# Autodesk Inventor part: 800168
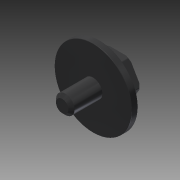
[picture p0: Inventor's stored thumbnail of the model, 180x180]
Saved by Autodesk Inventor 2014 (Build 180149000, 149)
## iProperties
Created: 2007-10
Part Number: 800168
Document SubType Name: Modeling
Designer: AL
Density: 8.08 g/cm^3
Mass: 16.5411 g
Surface Area: 16.0193 cm^2
Volume: 2.04717 cm^3
Material: Stainless Steel
Description: SCREW
Appearance: Rubber - Black - Version 1.1
Component Category: Fasteners
Author: AL
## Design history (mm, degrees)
sketch "Sketch1"
  geometry: L1 (0, -13.662)-(0, 11.973) reference; L2 (-11.878, 0)-(16.593, 0) reference; L3 (0, 7)-(5.25, 7); L4 (5.25, 7)-(5.25, 2); L5 (5.25, 2)-(12.375, 2); L6 (12.5, 1.875)-(12.5, 0.125); L7 (12.375, 0)-(3, 0); L8 (3, 0)-(3, -9); L9 (3, -9)-(2, -10); L10 (2, -10)-(0, -10); A1 r 0.125 centre (12.375, 1.875) between (12.5, 1.875) and (12.375, 2); A2 r 0.125 centre (12.375, 0.125) between (12.375, 0) and (12.5, 0.125); 3 further points
  constraints: 16 end point, 6 point on line, 5 parallel, 4 point on circle, 4 tangent, 2 centre point, 2 perpendicular, 1 collinear, 1 equal radius
  dimensions: "d0" = 1 horizontal distance of L8.end L9.end; "d1" = 1 horizontal distance of L8.end L9.end; "d2" = 6 diameter of L8 L1; "d3" = 25 diameter of L6 L1; "d4" = 10.5 diameter of L4 L1; "d5" = 2 distance between parallel lines of L5 L7; "d7" = 10 distance between parallel lines of L10 L7; "d10" = 5 distance between parallel lines of L5 L3; "d12" = 0.125 radius of A1
revolve "Revolution1" sketch "Sketch1" stored, may be unused: angle "d11" = 90 deg
workplane "Work Plane1"
sketch "Sketch2"
  geometry: L1 (10.874, 0)-(-10.569, 0) reference; L2 (0, -9.1)-(0, 9.1) reference; L3 (-3.753, -6.5)-(-7.506, 0); L4 (-7.506, 0)-(-3.753, 6.5); L5 (-3.753, 6.5)-(3.753, 6.5); L6 (3.753, 6.5)-(7.506, 0); L7 (7.506, 0)-(3.753, -6.5); L8 (3.753, -6.5)-(-3.753, -6.5); C1 r 5.25 at (0, 0); 2 further points
  constraints: 12 end point, 2 coincident, 1 centre point, 1 parallel, 13 other
  dimensions: "d16" = 13 distance between parallel lines of L5 L8; "d17" = 10.5 diameter of C1
extrude "Extrusion1" join sketch "Sketch2" stored distance "d18" = 10; taper "d19" = 0 deg
fillet "Fillet1" dims "d20" = 0.25
workplane "Work Plane2"
sketch "Sketch3"
  geometry: L1 (-7.5, 7.5)-(-7.5, 8); L2 (-7.5, 8)-(-7, 8); L3 (0, -1.662)-(0, 9.973) reference; L4 (-9.373, 0)-(1.562, 0) reference; L5 (-7, 8)-(-7.5, 7.5); 1 further point
  constraints: 6 end point, 1 perpendicular
  dimensions: "d22" = 0.5 distance of L1.end L2.end; "d23" = 0.5 distance of L1.start L1.end; "d26" = 7.5 distance between parallel lines of L1 L3; "d27" = 8 distance between parallel lines of L4 L2
revolve "Revolution2" sketch "Sketch3" stored, may be unused: angle "d28" = 90 deg
body "Solid1"
other parameters: "d15" = 8, "d21" = 0
